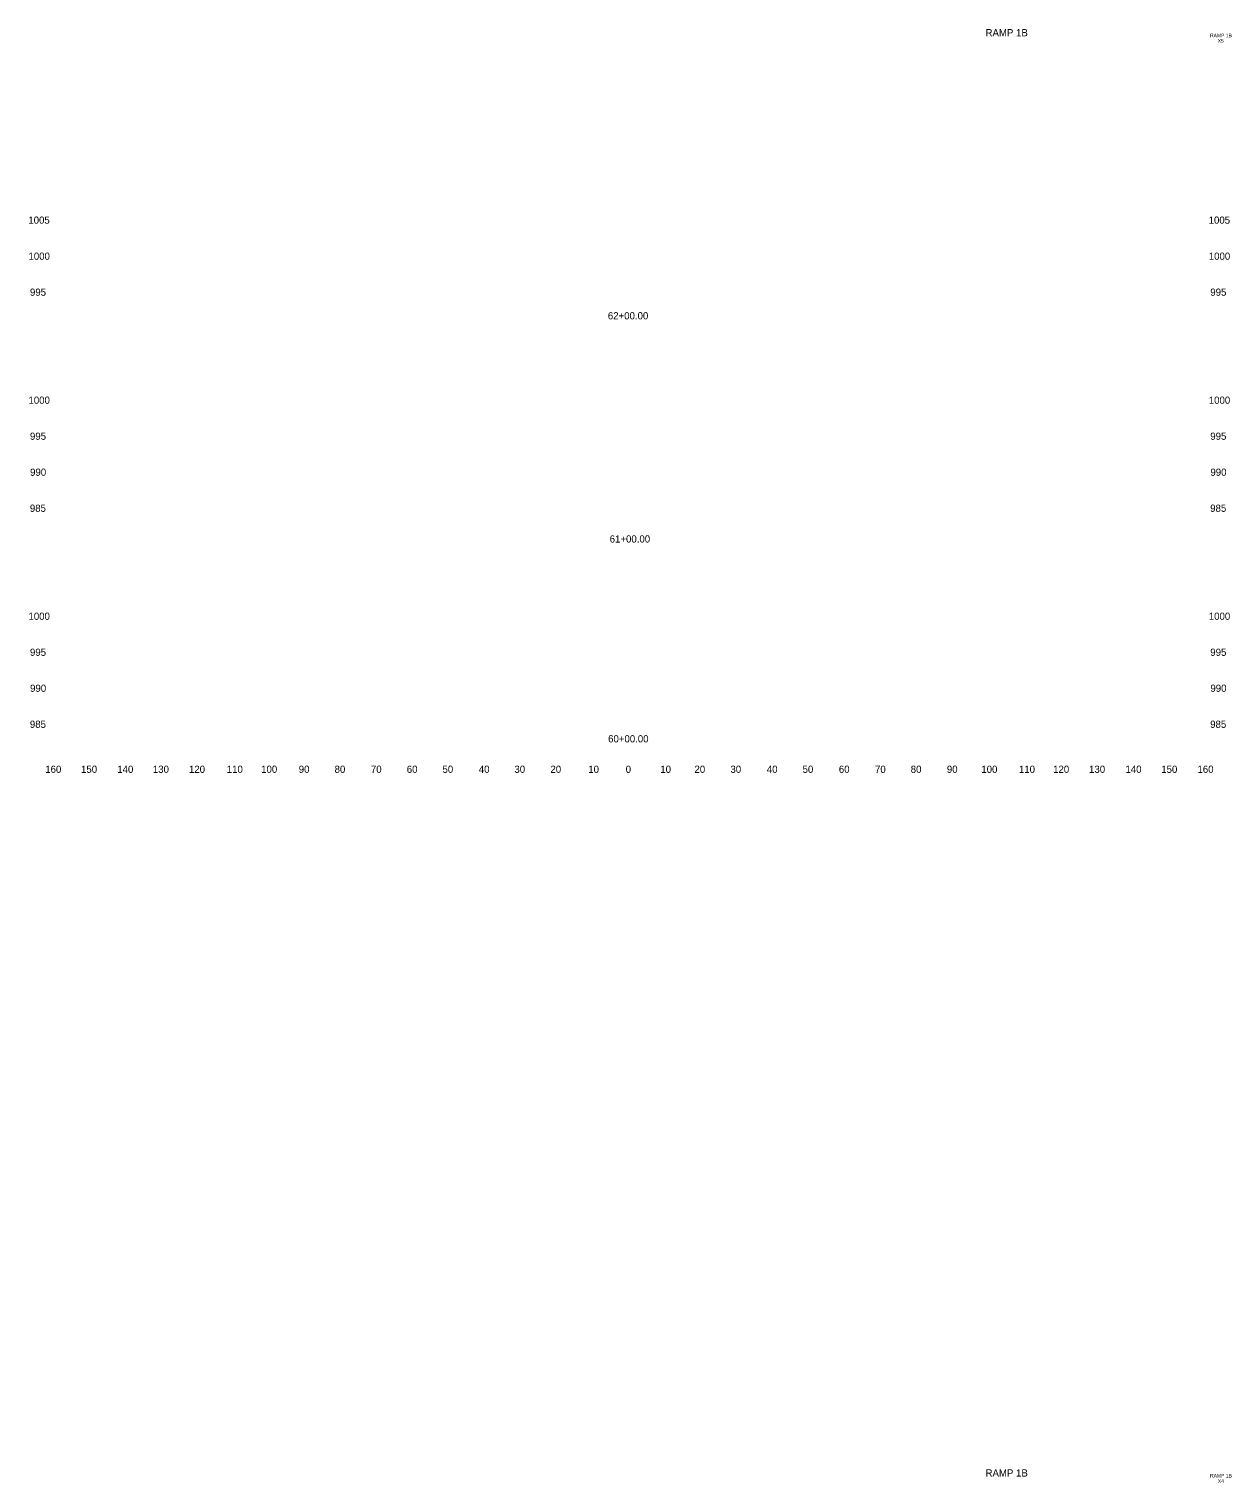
# Model space of a CAD drawing. Extents: x 4994 to 5843, y 4997 to 8804.
# Drawn here: x 4993.6 to 5327.4, y 6400.3 to 6804.1 of the extents above; entities that cross this region are included whole.
import ezdxf

# ---------------------------------------------------------------- set-up
doc = ezdxf.new("R2010")
doc.units = 0
for name, color, linetype in [('CLS_Search_Dist', 7, 'Continuous'), ('RD_XE_Ground', 7, 'Continuous'), ('UC_PD_Text', 7, 'Continuous')]:
    doc.layers.add(name, color=color, linetype=linetype)

msp = doc.modelspace()

# ---------------------------------------------------------------- texts
at = {"layer": 'CLS_Search_Dist'}
for s, p in [('1005', (4993.4, 6750)), ('1005', (5321.2, 6750)), ('1000', (4993.44, 6740)), ('1000', (5321.24, 6740)), ('995', (4993.86, 6730)), ('995', (5321.66, 6730)), ('1000', (4993.44, 6700)), ('1000', (5321.24, 6700)), ('995', (4993.86, 6690)), ('995', (5321.66, 6690)), ('990', (4993.89, 6680)), ('990', (5321.69, 6680)), ('985', (4993.83, 6670)), ('985', (5321.63, 6670)), ('1000', (4993.44, 6640)), ('1000', (5321.24, 6640)), ('995', (4993.86, 6630)), ('995', (5321.66, 6630)), ('990', (4993.89, 6620)), ('990', (5321.69, 6620)), ('985', (4993.83, 6610)), ('985', (5321.63, 6610)), ('160', (4998.1, 6597.5)), ('150', (5008.04, 6597.5)), ('140', (5018.1, 6597.5)), ('130', (5027.99, 6597.5)), ('120', (5038.01, 6597.5)), ('110', (5048.51, 6597.5)), ('100', (5058.07, 6597.5)), ('90', (5068.5, 6597.5)), ('80', (5078.46, 6597.5)), ('70', (5088.54, 6597.5)), ('60', (5098.5, 6597.5)), ('50', (5108.43, 6597.5)), ('40', (5118.5, 6597.5)), ('30', (5128.39, 6597.5)), ('20', (5138.4, 6597.5)), ('10', (5148.91, 6597.5)), ('0', (5159.3, 6597.5)), ('0', (5159.3, 6597.5)), ('10', (5168.91, 6597.5)), ('20', (5178.4, 6597.5)), ('30', (5188.39, 6597.5)), ('40', (5198.5, 6597.5)), ('50', (5208.43, 6597.5)), ('60', (5218.5, 6597.5)), ('70', (5228.54, 6597.5)), ('80', (5238.46, 6597.5)), ('90', (5248.5, 6597.5)), ('100', (5258.07, 6597.5)), ('110', (5268.51, 6597.5)), ('120', (5278.01, 6597.5)), ('130', (5287.99, 6597.5)), ('140', (5298.1, 6597.5)), ('150', (5308.04, 6597.5)), ('160', (5318.1, 6597.5))]:
    msp.add_text(s, height=2, dxfattribs=at).set_placement(p)
at = {"layer": 'RD_XE_Ground'}
for s, p in [('62+00.00', (5154.35, 6723.45)), ('61+00.00', (5154.86, 6661.46)), ('60+00.00', (5154.42, 6605.97))]:
    msp.add_text(s, height=2, dxfattribs=at).set_placement(p)
at = {"layer": 'UC_PD_Text'}
for s, height, p in [('RAMP 1B', 2, (5259.24, 6802.06)), ('RAMP 1B', 1, (5321.59, 6801.8)), ('X5', 1, (5323.74, 6800.3)), ('RAMP 1B', 2, (5259.24, 6402.06)), ('RAMP 1B', 1, (5321.59, 6401.8)), ('X4', 1, (5323.74, 6400.3))]:
    msp.add_text(s, height=height, dxfattribs=at).set_placement(p)

doc.saveas('drawing.dxf')
